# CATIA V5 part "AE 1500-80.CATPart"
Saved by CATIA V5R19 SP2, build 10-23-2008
Part number: AE 1500-80
Bounding box of the stored display mesh (mm): x -37.351 to 37.351, y -37.351 to 37.351, z 0 to 220
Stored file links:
  C:\Users\Bora\Desktop\3D Katı model\AE serisi\AE 1500\AE 1500-80.CATPart
  C:\Program Files\Dassault Systemes\B19\intel_a\reffiles\standard\MetricThickPitch.txt
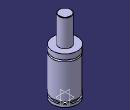
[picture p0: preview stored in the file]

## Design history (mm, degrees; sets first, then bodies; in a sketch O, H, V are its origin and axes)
Body1 (main body)
  Sketch1 on yz-plane, origin (0, 0, 0), H (0, 1, 0), V (0, 0, 1)
    point P1 (37.5, 123.5)
    point P5 (18, 219)
    point P7 (18, 219)
    point P12 (37.5, 118.5)
    point P13 (37.5, 123.5)
    point P14 (37.5, 118.5)
    line L1 (37.5, 123.5) -> (37.5, 139)
    line L2 (37.5, 0) -> (37.5, 8)
    arc A1 centre (17, 219) radius 1 from (18, 219) to (17, 220) ccw
    line L3 (18, 219) -> (18, 139)
    line L4 (33.5, 15) -> (33.5, 8)
    line L5 (37.5, 15) -> (37.5, 118.5)
    arc A2 centre (37.5, 121) radius 2.5 from (37.5, 123.5) to (37.5, 118.5) ccw
    line L6 (17, 220) -> (0, 220)
    point P15 (0, 220)
    line L7 (18, 139) -> (37.5, 139)
    line L8 (0, 0) -> (37.5, 0)
    line L9 (33.5, 15) -> (37.5, 15)
    line L10 (33.5, 8) -> (37.5, 8)
    coincidence: P15 V, P1 P13, P5 P7, P12 P14
    tangency: L6 A1
    horizontal: L7 H, L8 H, L9 H, L10 H
  Shaft1: profile Sketch1, axis Sketch1.V, angle 360
  Sketch2 on face of Shaft1 from Sketch1.L8, origin (0, 0, 0), H (1, 0, 0), V (0, -1, 0)
    point P1 (20, 0)
    distance P1 V = 20
  Hole1: placed by Sketch2, at (20, 0, 0) direction (0, 0, 1), diameter 6.647, depth 13, threaded "M8", thread diameter 8, thread depth 13, pitch 1.25
  CircPattern1: of Hole1, instances 4, angular step 90, axis from xy-plane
